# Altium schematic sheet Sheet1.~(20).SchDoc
size A3; SheetNumber: 1; SheetTotal: 2
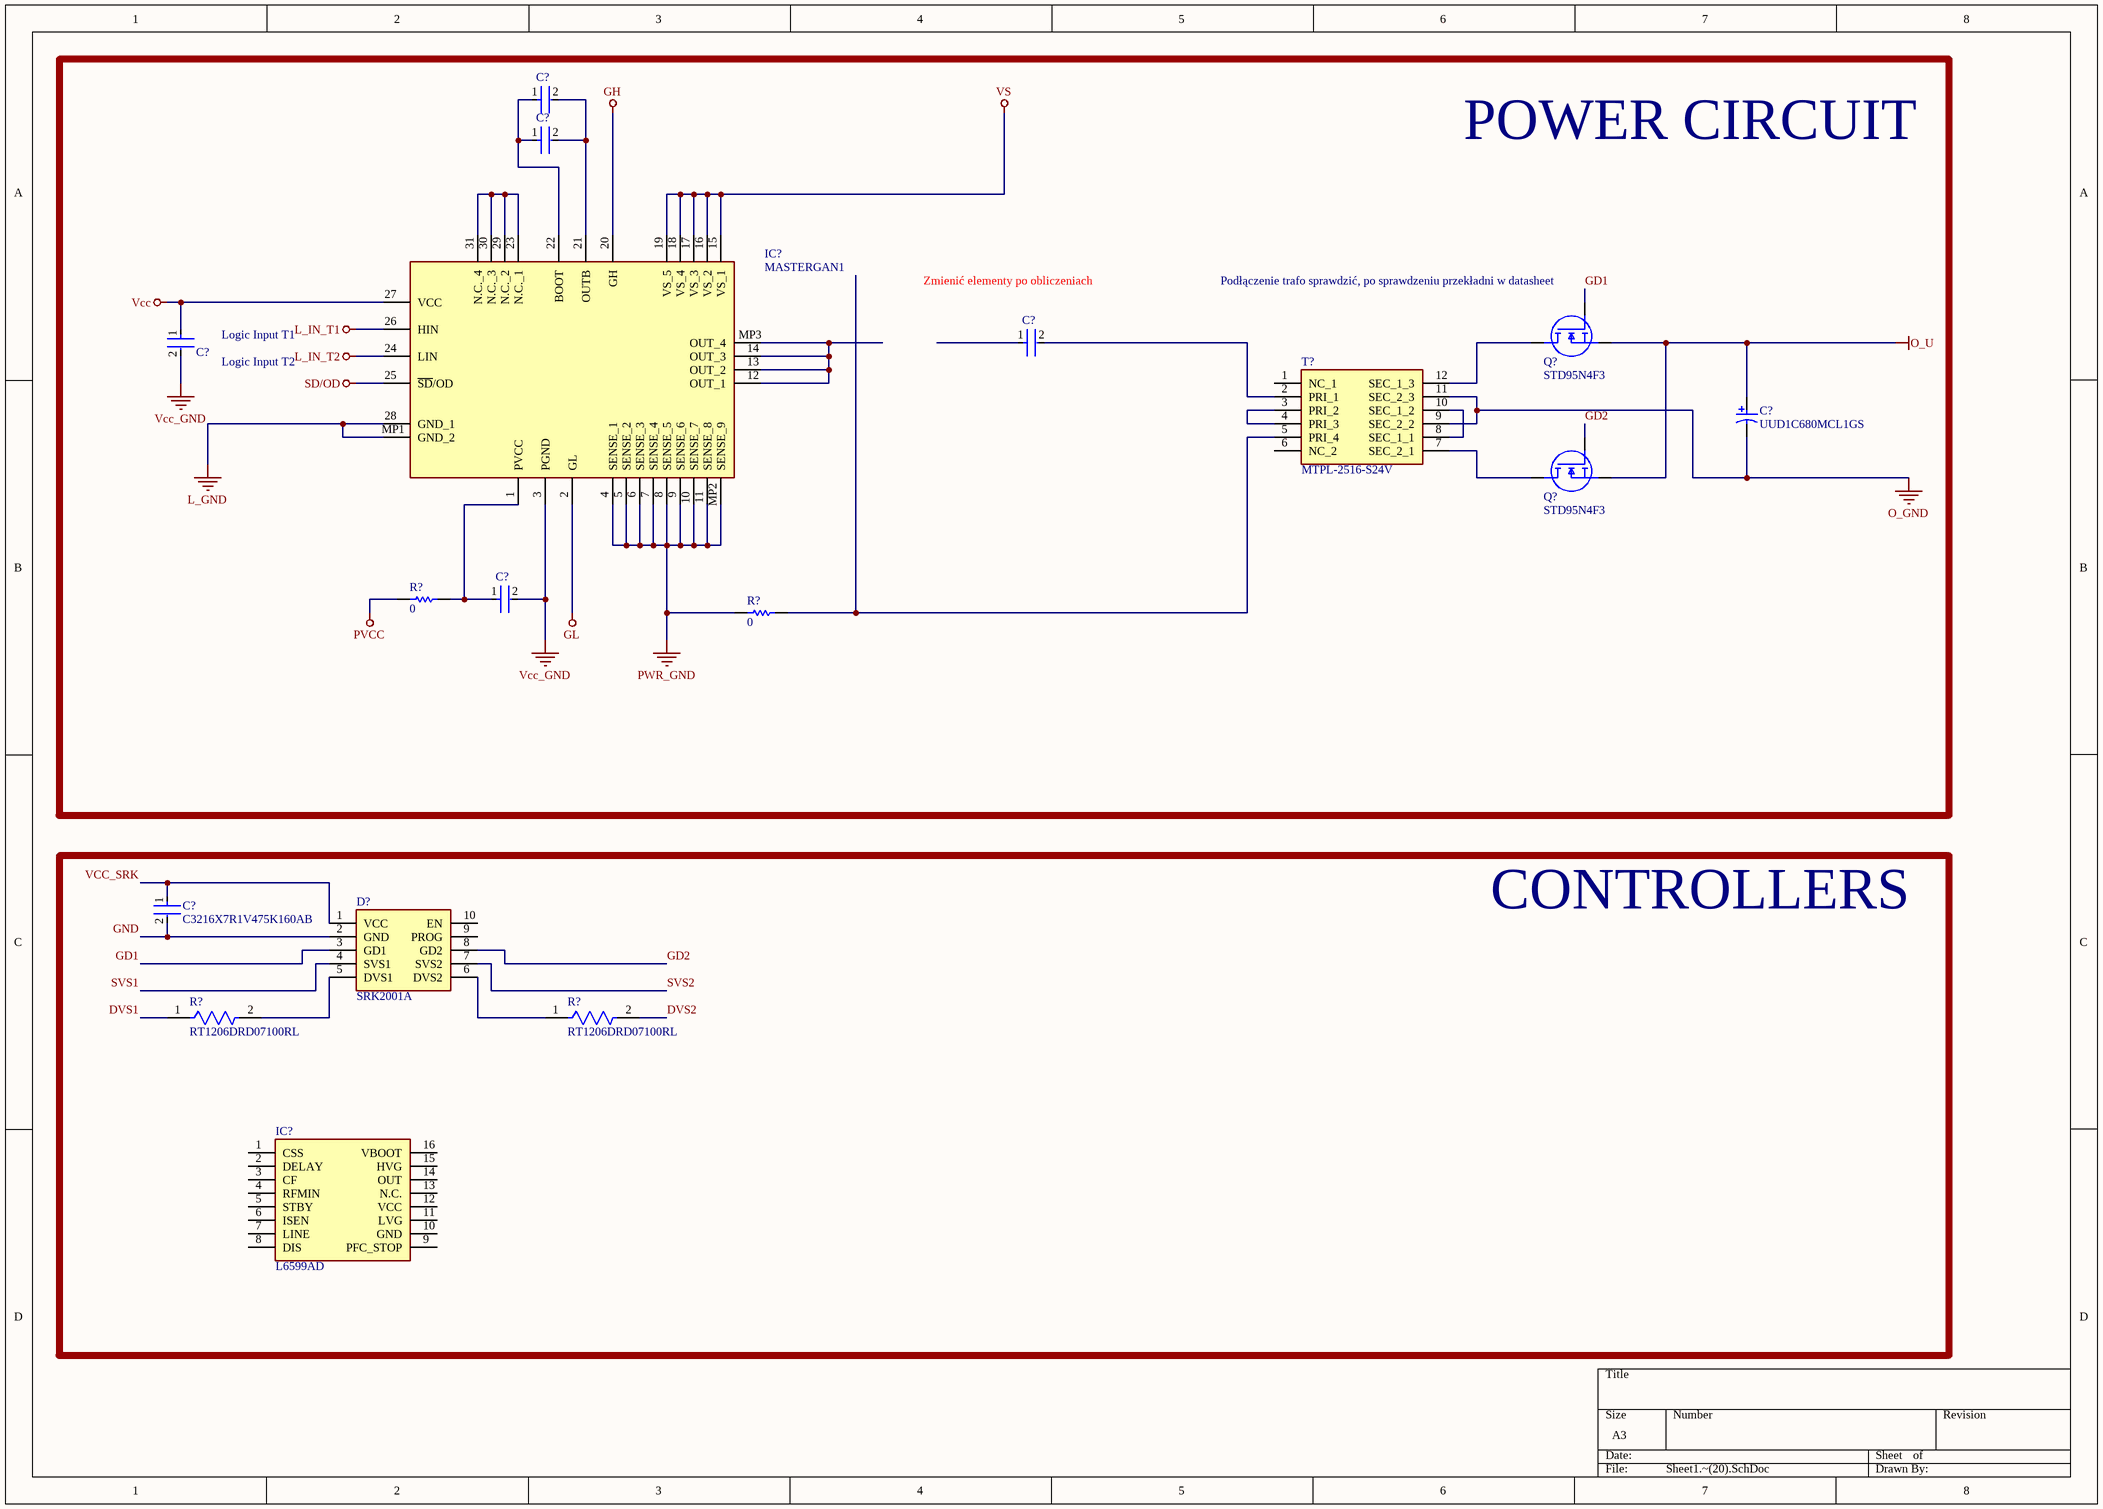
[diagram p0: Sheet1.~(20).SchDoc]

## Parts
(Parts that share a designator on the sheet are numbered #1, #2 ... from top to bottom, then left to right.)
C?#1  C3216X7R1V475K160AB  [FP-C3216-160-0_2-IPC_C]  (value not drawn)
C?#2  C3216X7R1V475K160AB  [FP-C3216-160-0_2-IPC_C]  (value not drawn)
C?#3  C3216X7R1V475K160AB  [FP-C3216-160-0_2-IPC_C]  (value not drawn)
C?#4  C3216X7R1V475K160AB  [FP-C3216-160-0_2-IPC_C]  (value not drawn)
C?#5  UUD1C680MCL1GS  [NIC-CAPA2-6.3X5.8_V]
C?#6  C3216X7R1V475K160AB  [FP-C3216-160-0_2-IPC_C]  (value not drawn)
C?#7  C3216X7R1V475K160AB  [FP-C3216-160-0_2-IPC_C]
D?  SRK2001A  [SOIC127P600X175-8N]
IC?#1  MASTERGAN1  [MASTERGAN1]
IC?#2  L6599AD  [SOIC127P600X175-16N]
Q?#1  STD95N4F3  [STD95N4F3]
Q?#2  STD95N4F3  [STD95N4F3]
R?#1  value 0  (hidden comment: Resistor)
R?#2  value 0  (hidden comment: Resistor)
R?#3  RT1206DRD07100RL  [FP-RT1206-MFG]
R?#4  RT1206DRD07100RL  [FP-RT1206-MFG]
T?  MTPL-2516-S24V  [MTPL2516S24V]

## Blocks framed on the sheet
POWER CIRCUIT: C?#1-C?#6 IC?#1 Q?#1 Q?#2 R?#1 R?#2 T?
CONTROLLERS: C?#7 D? IC?#2 R?#3 R?#4

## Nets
GH: IC?#1.20(GH)
GL: IC?#1.2(GL)
L_GND: IC?#1.28(GND_1) IC?#1.MP1(GND_2)
L_IN_T1: IC?#1.26(HIN)
L_IN_T2: IC?#1.24(LIN)
O_GND: C?#5.2 T?.9(SEC_2_2) T?.11(SEC_2_3)
O_U: C?#5.1 Q?#1.3(S) Q?#2.3(S)
PVCC: R?#1.1
PWR_GND: IC?#1.4(SENSE_1) IC?#1.5(SENSE_2) IC?#1.6(SENSE_3) IC?#1.7(SENSE_4) IC?#1.8(SENSE_5) IC?#1.9(SENSE_6) IC?#1.10(SENSE_7) IC?#1.11(SENSE_8) IC?#1.MP2(SENSE_9) R?#2.1
SD/OD: IC?#1.25(~{SD}/OD)
Vcc: C?#3.1 IC?#1.27(VCC)
Vcc_GND: C?#3.2 C?#6.2 IC?#1.3(PGND)
VS: IC?#1.15(VS_1) IC?#1.16(VS_2) IC?#1.17(VS_3) IC?#1.18(VS_4) IC?#1.19(VS_5)
DVS1: R?#3.1
DVS2: R?#4.2
GD1: D?.3(GD1) Q?#1.1(G)
GD2: D?.8(GD2) Q?#2.1(G)
GND: C?#7.2 D?.2(GND)
SVS1: D?.4(SVS1)
SVS2: D?.7(SVS2)
VCC_SRK: C?#7.1 D?.1(VCC)
NetC?#1_1: C?#1.1 C?#2.1 IC?#1.22(BOOT)
NetC?#1_2: C?#1.2 C?#2.2 IC?#1.21(OUTB)
NetC?#4_2: C?#4.2 T?.2(PRI_1)
NetC?#6_1: C?#6.1 IC?#1.1(PVCC) R?#1.2
NetD?_5: D?.5(DVS1) R?#3.2
NetD?_6: D?.6(DVS2) R?#4.1
NetIC?#1_12: IC?#1.12(OUT_1) IC?#1.13(OUT_2) IC?#1.14(OUT_3) IC?#1.MP3(OUT_4)
NetIC?#1_23: IC?#1.23(N.C._1) IC?#1.29(N.C._2) IC?#1.30(N.C._3) IC?#1.31(N.C._4)
NetQ?#1_4: Q?#1.4(D) T?.12(SEC_1_3)
NetQ?#2_4: Q?#2.4(D) T?.7(SEC_2_1)
NetR?#2_2: R?#2.2 T?.5(PRI_4)
NetT?_3: T?.3(PRI_2) T?.4(PRI_3)
NetT?_8: T?.8(SEC_1_1) T?.10(SEC_1_2)

Not connected (* = marked no-connect by the designer): C?#4 1; D? 9(PROG) 10(EN); IC?#2 1(CSS) 2(DELAY) 3(CF) 4(RFMIN) 5(STBY) 6(ISEN) 7(LINE) 8(DIS) 9(PFC_STOP) 10(GND) 11(LVG) 12(VCC) 13(N.C.) 14(OUT) 15(HVG) 16(VBOOT); T? 1(NC_1) 6(NC_2)

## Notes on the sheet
- Zmienić elementy po obliczeniach
- (near Q?#1) Podłączenie trafo sprawdzić, po sprawdzeniu przekładni w datasheet
- (near C?#3) Logic Input T1
- (near C?#3) Logic Input T2

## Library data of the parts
C?#1-C?#4 C?#6 C?#7 = CMP-08246-003663-1: Multilayer Ceramic Capacitors 4.7uF ±10% 35V X7R SMD 1206
C?#5 = CMP-0687-00035-1: Aluminum Electrolytic Capacitor, UD Series, Low Impedance, 68 uF, 16 V, + / - 20%, -55 to 105 degC, Chip Type, 6.3 x 5.8 mm D x L, Pb-Free, Reel; Manufacturer: Nichicon; Rated Voltage: 16 V; Endurance Time: 2000 h; Rated Ripple Current (at 100kHz): 230 mA; Rated Capacitance: 68 uF; Impedance: 0.44 Ohm; Packing: Dia382mm Reel; Tolerance Rated Capacitance: -20 to 20%
D? = SRK2001A: Diode; Manufacturer_Name: STMicroelectronics
IC?#1 = MASTERGAN1: Integrated Circuit; Manufacturer_Name: STMicroelectronics
IC?#2 = L6599AD: Integrated Circuit; Manufacturer_Name: STMicroelectronics
Q?#1 Q?#2 = STD95N4F3: MOSFET (N-Channel); Manufacturer_Name: STMicroelectronics
R?#1 R?#2 = Resistor: SimulationGenericComponent: True
R?#3 R?#4 = CMP-03412-027315-1: RES 100 OHM 1/4W .5% SMD 1206; Manufacturer: Yageo; Voltage Rating: 200V; Resistance: 100Ω; Power Rating: 0.25W; Value: 100Ω; Temperature Coefficient: 25 ppm/°C; Tolerance: 0.0001
T? = MTPL-2516-S24V: Transformer; Manufacturer_Name: Vishay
